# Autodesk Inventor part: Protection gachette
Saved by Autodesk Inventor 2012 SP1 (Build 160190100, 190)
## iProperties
Created: 2014-12
Part Number: Protection gachette
Material: Default
Document SubType Name: Modeling
Designer: Bruno
Density: 1 g/cm^3
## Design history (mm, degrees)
node "Protection gachette1"
node "Protection gachette"
node "Base1"
